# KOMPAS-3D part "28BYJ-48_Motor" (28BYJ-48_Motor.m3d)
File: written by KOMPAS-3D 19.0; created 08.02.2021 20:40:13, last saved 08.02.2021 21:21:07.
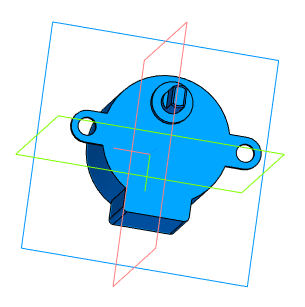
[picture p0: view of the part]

Document properties: Автор: Agent Smith; Полное имя файла: D:\3D_print\3D проекты Компас 3D\Халява Projects 5\28BYJ-48_Motor.m3d

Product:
- Part/product: 28BYJ-48_Motor
    Масса: 0.100949

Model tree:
1. Эскиз:1
2. Элемент выдавливания:1
     Расстояние 1 = 19
3. Эскиз:2  (with: Элемент выдавливания:1)
4. Элемент выдавливания:2
     Расстояние 2 = 0.8
5. Эскиз:3  (with: Элемент выдавливания:1)
6. Элемент выдавливания:3
     Расстояние 1 = 1.5
7. Эскиз:4  (with: Элемент выдавливания:3)
8. Элемент выдавливания:4
     Расстояние 1 = 2
9. Эскиз:5  (with: Элемент выдавливания:4)
10. Элемент выдавливания:5
     Расстояние 1 = 6
11. Скругление:1  (with: Элемент выдавливания:5)
     Радиус = 0.4
12. Эскиз:6  (with: Элемент выдавливания:1)
13. Элемент выдавливания:6
     Расстояние 2 = 16.6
